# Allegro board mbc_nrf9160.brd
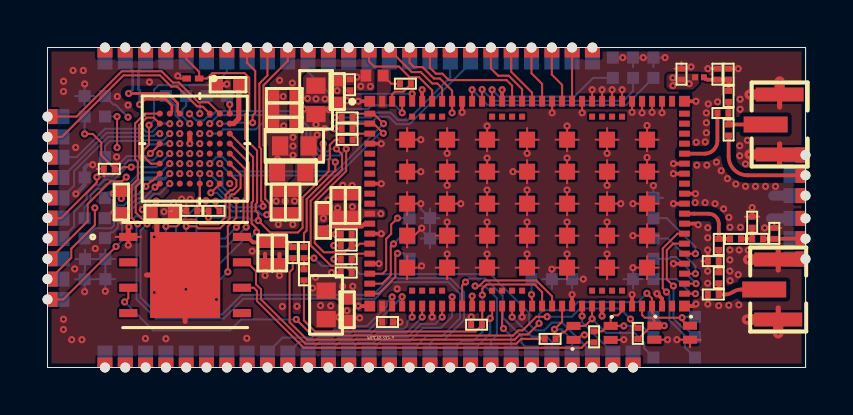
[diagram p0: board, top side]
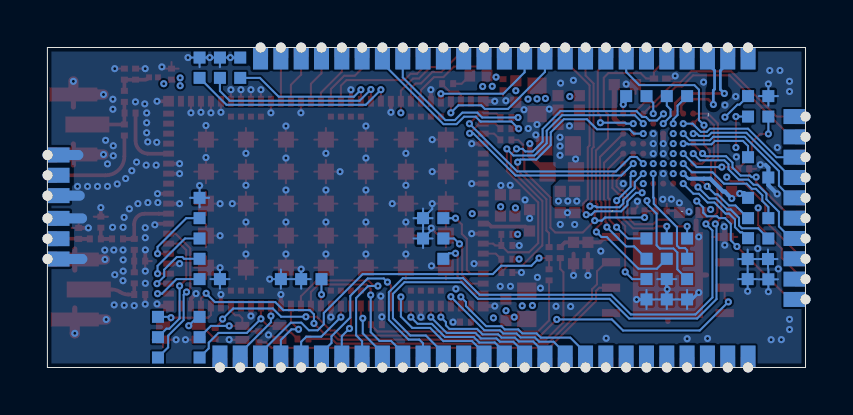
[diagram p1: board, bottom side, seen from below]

Outline 37.92 x 16 mm; copper layers: TOP, GND, POWER, BOTTOM. Coordinates in mm from the lower left corner of the outline.
Outline path: 0,16 0,0 37.92,0 37.92,16 0,16

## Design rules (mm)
constraint set DEFAULT: min track width 0.102
net group DIFFPAIR0: nets D+ D-

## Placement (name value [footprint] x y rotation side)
C1  39pF  [SMC0201]  33.51 14.94 270 top
C2  39pF  [SMC0201]  34.06 12.72 180 top
C3  15pF  [SMC0201]  15.13 13.86 90 top
C4  100nF  [SMC0402]  14.49 13.26 90 top
C5  47uF  [SMC0603]  13.43 12.67 90 top
C6  39pF  [SMC0201]  34.07 11.6 90 top
C7  100nF  [SMC0402]  14.54 8.64 270 top
C8  4.7uF  [SMC0402]  15.26 8.64 270 top
C9  4.7uF  [SMC0402]  13.8 7.89 270 top
C10  15pF  [SMC0201]  17.28 2.27 180 top
C11  100nF  [SMC0402]  14.99 3.42 270 top
C12  47uF  [SMC0603]  13.94 3.84 270 top
C13  100nF  [SMC0201]  21.19 2.14 0 top
C14  100nF  [SMC0201]  8.6 7.83 180 top
C15  100n  [SMC0402]  12.38 13.59 180 top
C16  100n  [SMC0402]  12.38 12.87 180 top
C17  100n  [SMC0402]  5.23 7.75 0 top
C18  100n  [SMC0402]  12.38 12.15 180 top
C19  10u  [SMC0603]  13.06 11.08 180 top
C20  100n  [SMC0402]  12.27 7.74 90 top
C21  1u  [SMC0402]  11.55 7.74 90 top
C22  100n  [SMC0402]  3.69 7.74 90 top
C23  4.7u  [SMC0402]  8.5 14.14 0 top
C24  100n  [SMC0402]  11.6 5.19 90 top
C25  1u  [SMC0402]  10.88 5.19 90 top
C65  TBD  [SMC0201]  35.25 6.43 0 top
C66  TBD  [SMC0201]  33.58 4.76 270 top
C67  680pF  [SMC0201]  31.71 14.94 270 top
C68  2.2nF  [SMC0201]  34.07 14.94 270 top
D1  PTVS5V5D1BLYL  [PESD5V0S1BL315]  26.31 1.73 90 top
D2  PTVS5V5D1BLYL  [PESD5V0S1BL315]  28.17 1.73 270 top
D3  PTVS5V5D1BLYL  [PESD5V0S1BL315]  30.36 1.74 270 top
D4  PTVS5V5D1BLYL  [PESD5V0S1BL315]  32.14 1.74 270 top
D5  ESDALC6V1-1U2  [DIODE_ESDALC6V1-1U2]  7.27 14.45 180 top
FL1  BLM15AX121SN1D  [BEADC1005X55N]  16.36 14.59 0 top
FL2  BLM02KX180SN1B  [BEADC0402X32N]  32.61 14.51 0 top
FL3  BLM18PG471SN1D  [SML0603]  11.48 9.78 0 top
J1  CON1  [MBC_PAD_CONN]  27.26 16 90 top
J2  CON1  [MBC_PAD_CONN]  26.24 16 90 top
J3  CON1  [MBC_PAD_CONN]  25.23 16 90 top
J4  CON1  [MBC_PAD_CONN]  24.21 16 90 top
J5  CON1  [MBC_PAD_CONN]  23.19 16 90 top
J6  CON1  [MBC_PAD_CONN]  22.18 16 90 top
J7  CON1  [MBC_PAD_CONN]  21.16 16 90 top
J8  CON1  [MBC_PAD_CONN]  20.15 16 90 top
J9  CON1  [MBC_PAD_CONN]  19.13 16 90 top
J10  CON1  [MBC_PAD_CONN]  18.11 16 90 top
J11  CON1  [MBC_PAD_CONN]  17.1 16 90 top
J12  CON1  [MBC_PAD_CONN]  16.08 16 90 top
J13  CON1  [MBC_PAD_CONN]  15.07 16 90 top
J14  CON1  [MBC_PAD_CONN]  14.05 16 90 top
J15  CON1  [MBC_PAD_CONN]  13.03 16 90 top
J16  CON1  [MBC_PAD_CONN]  12.02 16 90 top
J17  CON1  [MBC_PAD_CONN]  11 16 90 top
J18  CON1  [MBC_PAD_CONN]  9.99 16 90 top
J19  CON1  [MBC_PAD_CONN]  8.97 16 90 top
J20  CON1  [MBC_PAD_CONN]  7.95 16 90 top
J21  CON1  [MBC_PAD_CONN]  6.94 16 90 top
J22  CON1  [MBC_PAD_CONN]  5.92 16 90 top
J23  CON1  [MBC_PAD_CONN]  4.91 16 90 top
J24  CON1  [MBC_PAD_CONN]  3.89 16 90 top
J25  CON1  [MBC_PAD_CONN]  2.87 16 90 top
J26  CON1  [MBC_PAD_CONN]  0 12.55 180 top
J27  CON1  [MBC_PAD_CONN]  0 11.53 180 top
J28  CON1  [MBC_PAD_CONN]  0 10.52 180 top
J29  CON1  [MBC_PAD_CONN]  0 9.5 180 top
J30  CON1  [MBC_PAD_CONN]  0 8.48 180 top
J31  CON1  [MBC_PAD_CONN]  0 7.47 180 top
J32  CON1  [MBC_PAD_CONN]  0 6.45 180 top
J33  CON1  [MBC_PAD_CONN]  0 5.43 180 top
J34  CON1  [MBC_PAD_CONN]  0 4.42 180 top
J35  CON1  [MBC_PAD_CONN]  0 3.4 180 top
J36  CON1  [MBC_PAD_CONN]  2.88 0 270 top
J37  CON1  [MBC_PAD_CONN]  3.89 0 270 top
J38  CON1  [MBC_PAD_CONN]  4.91 0 270 top
J39  CON1  [MBC_PAD_CONN]  5.92 0 270 top
J40  CON1  [MBC_PAD_CONN]  6.94 0 270 top
J41  CON1  [MBC_PAD_CONN]  7.96 0 270 top
J42  CON1  [MBC_PAD_CONN]  8.97 0 270 top
J43  CON1  [MBC_PAD_CONN]  9.99 0 270 top
J44  CON1  [MBC_PAD_CONN]  11 0 270 top
J45  CON1  [MBC_PAD_CONN]  12.02 0 270 top
J46  CON1  [MBC_PAD_CONN]  13.04 0 270 top
J47  CON1  [MBC_PAD_CONN]  14.05 0 270 top
J48  CON1  [MBC_PAD_CONN]  15.07 0 270 top
J49  CON1  [MBC_PAD_CONN]  16.08 0 270 top
J50  CON1  [MBC_PAD_CONN]  17.1 0 270 top
J51  CON1  [MBC_PAD_CONN]  18.11 0 270 top
J52  CON1  [MBC_PAD_CONN]  19.13 0 270 top
J53  CON1  [MBC_PAD_CONN]  20.15 0 270 top
J54  CON1  [MBC_PAD_CONN]  21.16 0 270 top
J55  CON1  [MBC_PAD_CONN]  22.18 0 270 top
J56  CON1  [MBC_PAD_CONN]  23.2 0 270 top
J57  CON1  [MBC_PAD_CONN]  24.21 0 270 top
J58  CON1  [MBC_PAD_CONN]  25.23 0 270 top
J59  CON1  [MBC_PAD_CONN]  26.24 0 270 top
J60  CON1  [MBC_PAD_CONN]  27.26 0 270 top
J61  CON1  [MBC_PAD_CONN]  28.27 0 270 top
J62  CON1  [MBC_PAD_CONN]  29.29 0 270 top
J63  CON1  [MBC_PAD_CONN]  37.92 6.44 0 top
J64  CON1  [MBC_PAD_CONN]  37.91 9.61 0 top
J65  UFL  [U_FL-R-SMT-1]  36.55 3.9 180 top
J66  UFL  [U_FL-R-SMT-1]  36.62 12.15 180 top
J67  CON1  [MBC_PAD_CONN]  37.91 5.42 0 top
J68  CON1  [MBC_PAD_CONN]  37.91 7.46 0 top
J69  CON1  [MBC_PAD_CONN]  37.91 10.62 0 top
J70  CON1  [MBC_PAD_CONN]  37.91 8.59 0 top
J72  CON1  [MBC_LGA_SMALL_PAD]  7.95 13.57 180 bottom
J73  CON1  [MBC_LGA_SMALL_PAD]  2.87 12.55 180 bottom
J74  CON1  [MBC_LGA_SMALL_PAD]  2.87 7.47 180 bottom
J75  CON1  [MBC_LGA_SMALL_PAD]  5.92 4.42 180 bottom
J76  CON1  [MBC_LGA_SMALL_PAD]  5.92 5.43 180 bottom
J77  CON1  [MBC_LGA_SMALL_PAD]  7.95 5.43 180 bottom
J78  CON1  [MBC_LGA_SMALL_PAD]  6.94 5.43 180 bottom
J81  CON1  [MBC_LGA_SMALL_PAD]  1.86 9.5 180 bottom
J82  CON1  [MBC_LGA_SMALL_PAD]  7.95 3.4 180 bottom
J83  CON1  [MBC_LGA_SMALL_PAD]  2.87 10.52 180 bottom
J84  CON1  [MBC_LGA_SMALL_PAD]  2.87 8.48 180 bottom
J85  CON1  [MBC_LGA_SMALL_PAD]  6.94 13.57 180 bottom
J86  CON1  [MBC_LGA_SMALL_PAD]  7.95 4.42 180 bottom
J87  CON1  [MBC_LGA_SMALL_PAD]  5.92 13.57 180 bottom
J88  CON1  [MBC_LGA_SMALL_PAD]  5.92 6.45 90 bottom
J89  CON1  [MBC_LGA_SMALL_PAD]  2.87 13.57 180 bottom
J90  CON1  [MBC_LGA_SMALL_PAD]  6.94 6.45 90 bottom
J91  CON1  [MBC_LGA_SMALL_PAD]  1.86 7.47 180 bottom
J93  CON1  [MBC_LGA_SMALL_PAD]  8.97 13.57 180 bottom
J95  CON1  [MBC_LGA_SMALL_PAD]  1.86 12.55 180 bottom
J96  CON1  [MBC_LGA_SMALL_PAD]  7.95 6.45 90 bottom
J97  CON1  [MBC_LGA_SMALL_PAD]  1.86 6.45 180 bottom
J98  CON1  [MBC_LGA_SMALL_PAD]  2.89 5.42 180 bottom
J99  CON1  [MBC_LGA_SMALL_PAD]  2.87 6.47 180 bottom
J100  CON1  [MBC_LGA_SMALL_PAD]  1.88 5.42 180 bottom
J101  CON1  [MBC_LGA_SMALL_PAD]  1.86 13.57 180 bottom
J102  CON1  [MBC_LGA_SMALL_PAD]  1.86 4.41 180 bottom
J103  CON1  [MBC_LGA_SMALL_PAD]  18.11 7.47 180 bottom
J104  CON1  [MBC_LGA_SMALL_PAD]  5.92 3.4 180 bottom
J105  CON1  [MBC_LGA_SMALL_PAD]  18.11 6.45 180 bottom
J106  CON1  [MBC_LGA_SMALL_PAD]  2.89 4.42 180 bottom
J107  CON1  [MBC_LGA_SMALL_PAD]  18.11 5.43 180 bottom
J108  CON1  [MBC_LGA_SMALL_PAD]  6.94 4.42 180 bottom
J109  CON1  [MBC_LGA_SMALL_PAD]  29.29 4.42 180 bottom
J110  CON1  [MBC_LGA_SMALL_PAD]  6.94 3.4 180 bottom
J111  CON1  [MBC_LGA_SMALL_PAD]  26.24 4.42 180 bottom
J112  CON1  [MBC_LGA_SMALL_PAD]  32.39 1.52 180 bottom
J113  CON1  [MBC_LGA_SMALL_PAD]  25.23 4.42 180 bottom
J114  CON1  [MBC_LGA_SMALL_PAD]  32.39 0.5 180 bottom
J115  CON1  [MBC_LGA_SMALL_PAD]  19.13 7.47 180 bottom
J116  CON1  [MBC_LGA_SMALL_PAD]  30.31 7.47 180 bottom
J117  CON1  [MBC_LGA_SMALL_PAD]  19.13 6.45 180 bottom
J118  CON1  [MBC_LGA_SMALL_PAD]  30.31 6.45 180 bottom
J119  CON1  [MBC_LGA_SMALL_PAD]  30.31 14.48 180 bottom
J120  CON1  [MBC_LGA_SMALL_PAD]  30.31 5.43 180 bottom
J121  CON1  [MBC_LGA_SMALL_PAD]  29.29 14.48 180 bottom
J122  CON1  [MBC_LGA_SMALL_PAD]  30.31 4.42 180 bottom
J123  CON1  [MBC_LGA_SMALL_PAD]  28.27 14.48 180 bottom
J124  CON1  [MBC_LGA_SMALL_PAD]  24.21 4.42 180 bottom
J125  CON1  [MBC_LGA_SMALL_PAD]  30.31 15.5 180 bottom
J126  CON1  [MBC_LGA_SMALL_PAD]  30.31 0.5 180 bottom
J127  CON1  [MBC_LGA_SMALL_PAD]  29.29 15.5 180 bottom
J128  CON1  [MBC_LGA_SMALL_PAD]  30.31 1.52 180 bottom
J129  CON1  [MBC_LGA_SMALL_PAD]  28.27 15.5 180 bottom
J130  CON1  [MBC_LGA_SMALL_PAD]  30.31 2.53 180 bottom
J131  CON1  [MBC_LGA_SMALL_PAD]  32.39 2.53 180 bottom
J132  CON1  [MBC_LGA_SMALL_PAD]  30.31 8.48 180 bottom
L1  68nH  [SML0201]  34.07 13.28 90 top
L2  TBD  [SML0201]  35.25 6.99 90 top
L3  TBD  [SML0201]  36.36 6.43 90 top
L4  TBD  [SML0201]  33.58 5.32 180 top
L5  TBD  [SML0201]  33.58 3.65 180 top
R1  100  [SMR0201]  15.26 12.5 180 top
R2  100  [SMR0201]  15.26 11.94 180 top
R3  10k  [SMR0201]  17.63 14.19 0 top
R4  1k  [SMR0201]  14.71 11.38 0 top
R5  1k  [SMR0201]  12.83 4.36 90 top
R6  220  [SMR0201]  12.83 5.47 90 top
R7  10k  [SMR0201]  2.81 9.94 0 top
R8  100k  [SMR0201]  7.49 7.83 180 top
R9  0R  [SMR0201]  34.69 6.43 180 top
R10  0R  [SMR0201]  33.58 6.43 270 top
R21  100k  [SMR0201]  15.22 6.66 180 top
R22  100k  [SMR0201]  15.22 5.42 180 top
R23  NM  [SMR0201]  14.67 6.1 0 top
R24  NM  [SMR0201]  14.67 4.75 0 top
R25  0  [SMR0201]  25.41 1.43 180 top
R26  0  [SMR0201]  27.34 1.81 270 top
R27  0  [SMR0201]  29.53 1.43 90 top
R28  0  [SMR0201]  12.27 5.47 90 top
U1  NRF9160-SICA-R  [XCVR_NRF9160-SICA-R]  23.99 8.19 0 top
U3  ST4SIM-200M  [SON_IM-200M_STM]  6.89 4.62 0 top
U4  STM32U545REI6  [UFBGA64_5X5MM_STM]  7.37 10.94 90 top

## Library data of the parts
C1-C25 C67 C68 = C
C65 C66 = CAP NP_1
D1-D4 = PTVS5V5D1BLYL_0
D5 = ESDALC6V1-1U2
FL1 = BLM15AX121SN1D
FL2 = BLM02KX180SN1B
FL3 L2-L5 = INDUCTOR
J1-J64 J67-J70 J72-J78 J81-J91 J93 J95-J132 = CON1_2
J65 J66 = UFL
L1 = L
R1-R3 R5 R7-R10 R21-R28 = R
R4 R6 = R_0
U1 = myNRF9160-SICA-R_6
U3 = ST4SIM-200M_8: User Part Number: PN; Tolerance: TOL
U4 = STM32U545REI6_13: User Part Number: PN; Tolerance: TOL

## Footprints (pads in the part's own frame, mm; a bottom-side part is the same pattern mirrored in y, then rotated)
BEADC0402X32N
  rect 0.29x0.3 smd: 1(-0.222,0) 2(0.222,0)
BEADC1005X55N
  rect 0.54x0.6 smd: 1(-0.432,0) 2(0.432,0)
DIODE_ESDALC6V1-1U2
  rect 0.425x0.3 smd: 1(-0.312,0) 2(0.312,0)
MBC_LGA_SMALL_PAD
  rect 0.6x0.6 smd: 1(0,0)
MBC_PAD_CONN
  rect 0.5x0.75 hole 0.6: 1(0,0)
PESD5V0S1BL315
  rect 0.4x0.7 smd: 1(-0.35,0) 2(0.35,0)
SMC0201
  rect 0.3x0.35 smd: 1(0,0) 2(0.55,0)
SMC0402
  rect 0.559x0.559 smd: 1(0,0) 2(1.067,0)
SMC0603
  rect 0.813x0.965 smd: 1(0,0) 2(1.422,0)
SML0201
  rect 0.3x0.35 smd: 1(0,0) 2(0.55,0)
SML0603
  rect 0.813x0.965 smd: 1(0,0) 2(1.422,0)
SMR0201
  rect 0.3x0.35 smd: 1(0,0) 2(0.55,0)
SON_IM-200M_STM
  rect 0.91x0.407 smd: 1(-2.842,1.905) 2(-2.842,0.635) 3(-2.842,-0.635) 4(-2.842,-1.905) 5(2.842,-1.905) 6(2.842,-0.635) 7(2.842,0.635) 8(2.842,1.905)
  rect 3.505x4.293 smd: 9(0,0)
U_FL-R-SMT-1
  rect 2.4x0.7 smd: 1(0,1.5) 3(0,-1.5)
  rect 2.2x0.8 smd: 2(0.7,0)
UFBGA64_5X5MM_STM
  round 0.305 smd: A1(-1.75,1.75) A2(-1.25,1.75) A3(-0.75,1.75) A4(-0.25,1.75) A5(0.25,1.75) A6(0.75,1.75) A7(1.25,1.75) A8(1.75,1.75) B1(-1.75,1.25) B2(-1.25,1.25) B3(-0.75,1.25) B4(-0.25,1.25) B5(0.25,1.25) B6(0.75,1.25) B7(1.25,1.25) B8(1.75,1.25) C1(-1.75,0.75) C2(-1.25,0.75) C3(-0.75,0.75) C4(-0.25,0.75) C5(0.25,0.75) C6(0.75,0.75) C7(1.25,0.75) C8(1.75,0.75) D1(-1.75,0.25) D2(-1.25,0.25) D3(-0.75,0.25) D4(-0.25,0.25) D5(0.25,0.25) D6(0.75,0.25) D7(1.25,0.25) D8(1.75,0.25) E1(-1.75,-0.25) E2(-1.25,-0.25) E3(-0.75,-0.25) E4(-0.25,-0.25) E5(0.25,-0.25) E6(0.75,-0.25) E7(1.25,-0.25) E8(1.75,-0.25) F1(-1.75,-0.75) F2(-1.25,-0.75) F3(-0.75,-0.75) F4(-0.25,-0.75) F5(0.25,-0.75) F6(0.75,-0.75) F7(1.25,-0.75) F8(1.75,-0.75) G1(-1.75,-1.25) G2(-1.25,-1.25) G3(-0.75,-1.25) G4(-0.25,-1.25) G5(0.25,-1.25) G6(0.75,-1.25) G7(1.25,-1.25) G8(1.75,-1.25) H1(-1.75,-1.75) H2(-1.25,-1.75) H3(-0.75,-1.75) H4(-0.25,-1.75) H5(0.25,-1.75) H6(0.75,-1.75) H7(1.25,-1.75) H8(1.75,-1.75)
XCVR_NRF9160-SICA-R
  rect 0.54x0.54 smd: 1(-7.87,5.12) 21(-7.87,-5.12) 52(7.87,-5.12) 72(7.87,5.12)
  rect 0.54x0.3 smd: 2(-7.87,4.5) 3(-7.87,4) 4(-7.87,3.5) 5(-7.87,3) 6(-7.87,2.5) 7(-7.87,2) 8(-7.87,1.5) 9(-7.87,1) 10(-7.87,0.5) 11(-7.87,0) 12(-7.87,-0.5) 13(-7.87,-1) 14(-7.87,-1.5) 15(-7.87,-2) 16(-7.87,-2.5) 17(-7.87,-3) 18(-7.87,-3.5) 19(-7.87,-4) 20(-7.87,-4.5) 53(7.87,-4.5) 54(7.87,-4) 55(7.87,-3.5) 56(7.87,-3) 57(7.87,-2.5) 58(7.87,-2) 59(7.87,-1.5) 60(7.87,-1) 61(7.87,-0.5) 62(7.87,0) 63(7.87,0.5) 64(7.87,1) 65(7.87,1.5) 66(7.87,2) 67(7.87,2.5) 68(7.87,3) 69(7.87,3.5) 70(7.87,4) 71(7.87,4.5)
  rect 0.3x0.54 smd: 22(-7.25,-5.12) 23(-6.75,-5.12) 24(-6.25,-5.12) 25(-5.75,-5.12) 26(-5.25,-5.12) 27(-4.75,-5.12) 28(-4.25,-5.12) 29(-3.75,-5.12) 30(-3.25,-5.12) 31(-2.75,-5.12) 32(-2.25,-5.12) 33(-1.75,-5.12) 34(-1.25,-5.12) 35(-0.75,-5.12) 36(-0.25,-5.12) 37(0.25,-5.12) 38(0.75,-5.12) 39(1.25,-5.12) 40(1.75,-5.12) 41(2.25,-5.12) 42(2.75,-5.12) 43(3.25,-5.12) 44(3.75,-5.12) 45(4.25,-5.12) 46(4.75,-5.12) 47(5.25,-5.12) 48(5.75,-5.12) 49(6.25,-5.12) 50(6.75,-5.12) 51(7.25,-5.12) 73(7.25,5.12) 74(6.75,5.12) 75(6.25,5.12) 76(5.75,5.12) 77(5.25,5.12) 78(4.75,5.12) 79(4.25,5.12) 80(3.75,5.12) 81(3.25,5.12) 82(2.75,5.12) 83(2.25,5.12) 84(1.75,5.12) 85(1.25,5.12) 86(0.75,5.12) 87(0.25,5.12) 88(-0.25,5.12) 89(-0.75,5.12) 90(-1.25,5.12) 91(-1.75,5.12) 92(-2.25,5.12) 93(-2.75,5.12) 94(-3.25,5.12) 95(-3.75,5.12) 96(-4.25,5.12) 97(-4.75,5.12) 98(-5.25,5.12) 99(-5.75,5.12) 100(-6.25,5.12) 101(-6.75,5.12) 102(-7.25,5.12)
  rect 0.8x0.8 smd: 103_1(-6,3.2) 103_2(-4,3.2) 103_3(-2,3.2) 103_4(0,3.2) 103_5(2,3.2) 103_6(4,3.2) 103_7(6,3.2) 103_8(-6,1.6) 103_9(-4,1.6) 103_10(-2,1.6) 103_11(0,1.6) 103_12(2,1.6) 103_13(4,1.6) 103_14(6,1.6) 103_15(-6,0) 103_16(-4,0) 103_17(-2,0) 103_18(0,0) 103_19(2,0) 103_20(4,0) 103_21(6,0) 103_22(-6,-1.6) 103_23(-4,-1.6) 103_24(-2,-1.6) 103_25(0,-1.6) 103_26(2,-1.6) 103_27(4,-1.6) 103_28(6,-1.6) 103_29(-6,-3.2) 103_30(-4,-3.2) 103_31(-2,-3.2) 103_32(0,-3.2) 103_33(2,-3.2) 103_34(4,-3.2) 103_35(6,-3.2)
  rect 0.3x0.3 smd: 104(-5.75,-4.35) 105(-5.25,-4.35) 106(-4.75,-4.35) 107(-4.25,-4.35) 108(-1.75,-4.35) 109(-1.25,-4.35) 110(-0.75,-4.35) 111(-0.25,-4.35) 112(3.25,-4.35) 113(3.75,-4.35) 114(4.25,-4.35) 115(4.75,-4.35) 116(4.75,4.35) 117(4.25,4.35) 118(3.75,4.35) 119(3.25,4.35) 120(-0.25,4.35) 121(-0.75,4.35) 122(-1.25,4.35) 123(-1.75,4.35) 124(-4.25,4.35) 125(-4.75,4.35) 126(-5.25,4.35) 127(-5.75,4.35)

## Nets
GND: C1.1 C3.1 C4.1 C5.1 C7.1 C8.1 C9.1 C10.1 C11.1 C12.1 C13.1 C14.1 C15.1 C16.1 C17.1 C18.1 C19.1 C20.1 C21.1 C22.1 C23.1 C24.1 C25.1 C67.1 C68.1 D1.1 D2.2(K2) D3.2(K2) D4.2(K2) D5.2 J1.1 J13.1 J22.1 J25.1 J38.1 J39.1 J43.1 J50.1 J62.1 J65.1 J65.3 J66.1 J66.3 J67.1 J68.1 J69.1 J70.1 J81.1 J82.1 J98.1 J100.1 J101.1 J102.1 J104.1 J106.1 J108.1 J109.1 J110.1 J111.1 J113.1 J115.1 J117.1 J125.1 J127.1 J129.1 J132.1 L2.2 L3.2 L4.2 L5.2 R7.1 R23.1 R24.1 U1.1 U1.5 U1.9 U1.14 U1.17 U1.21 U1.27 U1.31 U1.36 U1.41 U1.44 U1.47 U1.50 U1.52 U1.56 U1.60 U1.62 U1.63 U1.65 U1.66 U1.72 U1.74 U1.75 U1.76 U1.77 U1.78 U1.79 U1.80 U1.81 U1.82 U1.85 U1.90 U1.94 U1.98 U1.103_1(VSS#103_1) U1.103_2 U1.103_3 U1.103_4 U1.103_5 U1.103_6 U1.103_7 U1.103_8 U1.103_9 U1.103_10 U1.103_11 U1.103_12 U1.103_13 U1.103_14 U1.103_15 U1.103_16 U1.103_17 U1.103_18 U1.103_19 U1.103_20 U1.103_21 U1.103_22 U1.103_23 U1.103_24 U1.103_25 U1.103_26 U1.103_27 U1.103_28 U1.103_29 U1.103_30 U1.103_31 U1.103_32 U1.103_33 U1.103_34 U1.103_35 U3.1 U3.9 U4.C2 U4.D4 U4.D5 U4.D6(VSS_4) U4.F1
VBAT: C22.2 J84.1 U4.B2
VDD: FL1.2 R3.1 U1.102
VDD NRF91: C3.2 C4.2 C5.2 C7.2 C8.2 C10.2 C11.2 C12.2 C67.2 FL1.1 FL2.1 J40.1 J41.1 J42.1 R21.2 R22.2 U1.12 U1.22
VDD_RF: C1.2 C68.2 FL2.2 L1.2
VDD_ST: C15.2 C16.2 C17.2 C18.2 C19.2 FL3.1 J36.1 J37.1 R8.2 U4.D2 U4.E4 U4.E5 U4.E6
VDDA_ST: C20.2 C21.2 FL3.2 J20.1 U4.H1
A0_N: J44.1 U1.23
A1_N: J45.1 U1.24
A2_N: J46.1 U1.25
A3_N: J47.1 U1.26
A4_N: J48.1 U1.28
A5_N: J49.1 U1.29
A6_N: J57.1 U1.30
A7_N: J58.1 U1.35
COEX0: J119.1 U1.93
COEX1: J121.1 U1.92
COEX2: J123.1 U1.91
D+: J23.1 U4.B8
D-: J24.1 U4.C8
ENABLE: R3.2 U1.101
ESIM_1V8: C24.2 C25.2 R28.2 U3.8(VCC)
ESIM_CLK: R26.2 U3.6
ESIM_IO: R27.2 U3.3
ESIM_RST: R25.2 U3.7
IO_SUPPLY_RSV: C9.2 U1.13
MAGPIO0: J118.1 U1.55
MAGPIO1: J120.1 U1.54
MAGPIO2: J122.1 U1.53
N_U545_NRST: R4.2 U1.4
NORDICRST: C13.2 R5.1 U1.32
NRF91_INT: R21.1 R23.2 U1.15 U4.F7
NRF91_RSTN: J60.1 R5.2 R6.1
NRF91_SWDCLK: J54.1 U1.33
NRF91_SWDIO: J56.1 U1.34
NRF91RST: R6.2 U4.F6
NRX: J8.1 R1.2
NTX: J7.1 R2.2
NTX_SRX: R2.1 U1.3 U4.G3
OSC32_IN: J97.1 U4.A1
OSC32_OUT: J99.1 U4.B1
OSC_IN: U4.C1
OSC_OUT: U4.D1
P0.00: J10.1 U1.95
P0.01: J11.1 U1.96
P0.02: J12.1 U1.97
P0.03: J14.1 U1.99
P0.04: J15.1 U1.100
P0.10: J103.1 U1.18
P0.11: J105.1 U1.19
P0.12: J107.1 U1.20
P0.21: J124.1 U1.37
P0.22: J53.1 U1.38
P0.23: J55.1 U1.39
P0.24: J59.1 U1.40
P0.25: J61.1 U1.42
P0.26: J2.1 U1.83
P0.27: J3.1 U1.84
P0.28: J4.1 U1.86
P0.29: J5.1 U1.87
P0.30: J6.1 U1.88
P0.31: J9.1 U1.89
PA0: J86.1 U4.G2
PA1: J88.1 U4.H2
PA4: J90.1 U4.H3
PA5: U4.F4
PA6: U4.G4
PA7: J96.1 U4.H4
PA8: J85.1 U4.D7
PA9: J87.1 U4.C7
PA10: J89.1 U4.C6
PA15: J29.1 U4.A6
PB0: U4.F5
PB1: U4.G5
PB2: U4.G6
PB3: J31.1 U4.A5
PB4: J32.1 U4.A4
PB5: J33.1 U4.C4
PB6: J35.1 U4.D3
PB7: J34.1 U4.C3
PB8: J91.1 U4.B3
PB9: J19.1 U4.A3
PB10: J18.1 U4.G7
PB12: J93.1 U4.H8
PB13: J26.1 U4.G8
PB14: J27.1 U4.F8
PC0: J75.1 U4.E3
PC1: J76.1 U4.E2
PC2: J17.1 U4.F2
PC3: J16.1 U4.G1
PC4: J77.1 U4.H5
PC5: J78.1 U4.H6
PC7: U4.E7
PC8: J72.1 U4.E8
PC10: J28.1 U4.B7
PC11: J30.1 U4.B6
PC12: J73.1 U4.C5
PC13: J74.1 U4.A2
PD2: J83.1 U4.B5
PH3: J95.1 R7.2 U4.B4
SCLK: J112.1 U1.58
SDATA: J114.1 U1.59
SIM_1V8: D4.1 J131.1 R28.1 U1.49
SIM_CLK: D2.1 J128.1 R26.1 U1.46
SIM_IO: D3.1 J130.1 R27.1 U1.48
SIM_RST: D1.2(K2) J126.1 R25.1 U1.43
STX_NRX: R1.1 U1.2 U4.F3
U545_INT: R22.1 R24.2 U1.16 U4.D8
U545_NRST: C14.2 D5.1(K) J21.1 R4.1 R8.1 U4.E1
U545_SWDCLK: J52.1 U4.A7
U545_SWDIO: J51.1 U4.A8
VCAP: C23.2 U4.H7
VIO: J116.1 U1.57
N13496579: C2.2 U1.67
N13625908: C66.2 J65.2(RF) L5.1
N13629219: C65.2 J63.1 L3.1
N13629615: C2.1 C6.2 J66.2(RF) L1.1
N13629622: C6.1 J64.1
N13657158: R9.2 R10.1 U1.61
N13657162: C65.1 L2.1 R9.1
N13659178: C66.1 L4.1 R10.2

Pads without a net: U1 6 7 8 10 11 45 51 64 68 69 70 71 73 104 105 106 107 108 109 110 111 112 113 114 115 116 117 118 119 120 121 122 123 124 125 126 127; U3 2 4 5

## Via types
v1: diameter 0.36, hole 0.15, TOP to BOTTOM, 351 vias

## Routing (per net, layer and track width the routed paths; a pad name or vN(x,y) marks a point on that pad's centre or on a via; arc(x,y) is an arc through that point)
GND: length 218.8
  TOP w0.102: 25.41,4.99 U1.103_33 ; U1.103_33 26.57,4.99 ; U1.103_33 25.99,4.41 ; U1.103_33 v1(25.99,5.67) ; 21.99,6.01 U1.103_24 ; U1.103_24 21.41,6.59 ; U1.103_24 v1(21.99,7.27) ; U1.103_24 22.57,6.59 ; U1.103_31 22.57,4.99 ; U1.103_31 21.41,4.99 ; U1.103_31 v1(21.99,5.67) ; 33.03,4.97 L4.2 32.7,5.32 ; v1(8.41,8.31) 8.41,8.02 C14.1 ; 19.99,7.61 U1.103_16 ; U1.103_16 19.99,8.77 ; U1.103_16 v1(20.67,8.19) ; U1.103_16 19.41,8.19 ; C67.1 32.1,14.94 32.19,15.03 v1(32.19,15.03) ; C67.1 31.36,14.94 ; C67.1 31.71,15.27 ; U1.103_4 v1(23.99,10.71) ; U1.103_4 23.41,11.39 ; U1.103_4 24.57,11.39 ; U1.103_4 23.99,11.97 ; U1.103_9 v1(19.99,9.11) ; U1.103_9 20.57,9.79 ; U1.103_9 19.41,9.79 ; U1.103_9 19.99,10.37 ; 19.99,6.01 U1.103_23 ; U1.103_23 19.41,6.59 ; U1.103_23 20.57,6.59 ; U1.103_23 v1(19.99,7.27) ; U1.103_17 22.57,8.19 ; U1.103_17 21.41,8.19 ; U1.103_17 v1(21.99,8.87) ; U1.103_17 21.99,7.61 ; D3.2 v1(31.01,1.39) ; U1.103_19 26.57,8.19 ; U1.103_19 v1(25.99,8.87) ; U1.103_19 25.41,8.19 ; U1.103_19 25.99,7.61 ; 32.14,1.01 D4.2 ; D4.2 v1(31.48,1.39) ; D4.2 32.67,1.39 ; 19.99,4.41 U1.103_30 ; U1.103_30 19.41,4.99 ; U1.103_30 v1(19.99,5.67) ; U1.103_30 20.57,4.99 ; 34.89,7.54 L2.2 35.6,7.54 ; U1.103_21 30.57,8.19 ; U1.103_21 29.99,8.77 ; U1.103_21 v1(29.28,8.19) ; U1.103_21 29.99,7.61 ; 2.46,9.94 R7.1 2.81,9.57 2.85,9.54 ; 27.41,6.59 U1.103_27 ; U1.103_27 28.57,6.59 ; U1.103_27 27.99,6.01 ; U1.103_27 v1(27.99,7.27) ; 17.99,7.61 U1.103_15 ; U1.103_15 17.99,8.77 ; U1.103_15 17.41,8.19 ; U1.103_15 v1(18.67,8.19) ; 25.99,9.21 U1.103_12 ; U1.103_12 26.57,9.79 ; U1.103_12 v1(25.99,10.47) ; U1.103_12 25.41,9.79 ; U1.103_6 28.57,11.39 ; U1.103_6 27.99,11.97 ; U1.103_6 v1(27.99,10.71) ; U1.103_6 27.41,11.39 ; U1.103_10 22.57,9.79 ; U1.103_10 21.41,9.79 ; U1.103_10 21.99,9.21 ; U1.103_10 v1(21.99,10.47) ; U1.103_25 24.57,6.59 ; U1.103_25 23.99,6.01 ; U1.103_25 23.41,6.59 ; U1.103_25 v1(23.99,7.27) ; U1.103_3 v1(21.99,12.07) ; U1.103_3 22.57,11.39 ; U1.103_3 21.99,10.81 ; U1.103_3 21.41,11.39 ; U1.103_11 23.99,10.37 ; U1.103_11 24.57,9.79 ; U1.103_11 v1(23.28,9.79) ; U1.103_11 23.99,9.21 ; U1.103_2 19.99,11.97 ; U1.103_2 20.57,11.39 ; U1.103_2 v1(19.99,10.71) ; U1.103_2 19.41,11.39 ; U1.103_14 v1(29.99,10.5) ; U1.103_14 29.99,9.21 ; U1.103_14 30.57,9.79 ; U1.103_14 29.41,9.79 ; U1.103_13 27.99,10.37 ; U1.103_13 27.41,9.79 ; U1.103_13 v1(27.99,9.11) ; U1.103_13 28.57,9.79 ; U1.103_29 17.99,5.57 ; U1.103_29 17.99,4.41 ; U1.103_29 18.62,4.99 v1(18.71,5.08) ; 27.41,4.99 U1.103_34 ; U1.103_34 28.57,4.99 ; U1.103_34 v1(27.99,5.67) ; U1.103_34 27.99,4.41 ; 23.99,7.61 U1.103_18 ; U1.103_18 24.57,8.19 ; U1.103_18 23.41,8.19 ; U1.103_18 v1(23.99,8.87) ; v1(28.83,1.39) 28.81,1.38 D2.2 ; 29.99,10.81 U1.103_7 ; U1.103_7 29.41,11.39 ; U1.103_7 30.57,11.39 ; U1.103_7 v1(29.99,12.1) ; 25.41,11.39 U1.103_5 ; U1.103_5 26.57,11.39 ; U1.103_5 25.99,10.81 ; U1.103_5 v1(25.99,12.07) ; U1.103_8 17.99,10.37 ; U1.103_8 17.99,9.21 ; U1.103_8 v1(18.67,9.79) ; U1.103_8 17.41,9.79 ; 29.99,6.01 U1.103_28 ; U1.103_28 v1(29.28,6.59) ; U1.103_28 30.57,6.59 ; U1.103_28 29.99,7.17 ; U1.103_26 26.57,6.59 ; U1.103_26 v1(25.99,7.27) ; U1.103_26 25.99,6.01 ; U1.103_26 25.41,6.59 ; U1.103_20 27.99,8.77 ; U1.103_20 27.99,7.61 ; U1.103_20 27.41,8.19 ; U1.103_20 v1(28.67,8.19) ; U1.17 16.13,5.19 ; U1.79 v1(28.24,13.89) ; 36.71,6.98 L3.2 36.36,7.31 ; v1(21.19,2.53) 21.19,2.53 C13.1 ; C68.1 v1(34.55,14.94) ; 8.04,14.14 C23.1 8.5,13.68 ; U1.103_35 29.99,5.57 ; U1.103_35 v1(29.28,4.99) ; U1.103_35 30.57,4.99 ; U1.103_35 29.99,4.41 ; 3.41,6.53 U3.1 4.68,6.53 ; C3.1 15.13,13.59 ; 17.99,10.81 U1.103_1 ; U1.103_1 17.99,11.97 ; U1.103_1 v1(18.67,11.39) ; U1.103_1 17.41,11.39 ; U1.76 v1(29.74,12.73) ; U1.81 v1(27.24,13.89) ; U1.75 v1(30.24,12.76) ; U1.85 v1(25.24,12.73) ; D5.2 6.65,14.45 v1(6.52,14.58) ; U1.82 v1(26.74,12.73) ; U1.103_32 v1(23.99,5.67) ; U1.103_32 23.41,4.99 ; U1.103_32 24.57,4.99 ; U1.103_22 18.34,6.59 v1(18.72,6.97) ; U1.103_22 17.99,6.01 ; U1.103_22 17.99,7.17 ; U1.80 v1(27.74,13.89) ; U1.74 v1(30.74,12.73) ; R24.1 v1(14.21,4.75) ; C1.1 v1(33.03,14.94) ; U1.77 v1(29.24,12.76) ; v1(14.32,6.1) R23.1 ; v1(26.86,1.63) 26.73,1.63 26.48,1.38 D1.1 ; U1.78 v1(28.74,13.89)
  TOP w0.188: L4.2 33.03,5.8 ; U1.14 v1(16.7,6.69) ; U1.66 v1(31.31,10.19) ; U1.41 v1(26.24,3.65) ; U1.56 v1(31.31,5.19) ; L3.2 v1(35.87,6.98) ; U1.5 v1(16.7,11.19) ; U1.50 30.74,3.44 v1(30.48,3.69) ; L5.2 v1(33.03,3.17) ; v1(18.74,13.89) U1.98 ; U1.65 v1(31.31,9.69) ; U1.31 21.24,3.57 v1(21.24,3.57) ; U1.94 v1(20.74,12.76) ; U1.9 v1(16.7,9.19) ; 16.13,5.19 v1(16.58,5.19) ; v1(15.54,13.31) U1.1 ; v1(22.74,13.89) U1.90 ; U1.72 v1(32.44,13.31) ; U1.62 v1(31.31,8.19) ; L2.2 v1(35.25,8) ; U1.63 v1(32.41,8.69) ; U1.27 v1(19.24,2.52) ; U1.52 32.32,3.07 32.43,3.18 v1(32.44,3.18) ; U1.36 v1(23.74,2.52) ; U1.44 v1(27.74,2.57) ; v1(29.24,3.65) U1.47 ; U1.60 32.41,7.19 ; v1(15.54,3.07) U1.21
  TOP w0.203: v1(10.88,4.6) C25.1 10.88,5.69 ; v1(11.6,4.6) C24.1 11.6,5.69 ; 3.69,7.25 C22.1 3.24,7.74 ; v1(4.04,6.12) 4.04,6.12 U3.1
  TOP w0.254: 36.55,4.87 J65.3 36.55,5.93 ; U3.9 4.95,4.62 ; U3.9 5.47,6.04 5.47,7.33 ; U3.9 6.89,2.3 ; J65.1 36.55,2.98 ; C23.1 8.94,14.14 v1(8.97,14.17) ; 36.62,11.18 J66.1 36.62,10.12 ; U3.1 4.04,7.02 v1(4.07,7.04) ; U4.D6 v1(7.12,11.19) ; J66.3 36.62,13.02
  TOP w0.508: v1(36.55,1.71) J65.1 v1(34.98,2.4) ; J66.1 v1(35.11,10.65) ; J65.3 v1(35.04,5.4) ; v1(35.11,13.65) J66.3 v1(36.62,14.31)
  GND w0.508: 5.92,14.16 J22.1 ; J62.1 29.29,1.21 ; 36.2,7.46 J68.1 ; 36.74,5.42 J67.1 ; 36.38,8.59 J70.1 ; 5.92,1.83 J39.1 ; 9.99,1.89 J43.1 ; 17.1,1.46 J50.1 ; 27.26,14.71 J1.1 ; J38.1 4.91,1.67 ; 2.87,14.19 J25.1 ; 36.58,10.62 J69.1 ; J13.1 15.07,15.25
  POWER w0.254: 29.29,0.85 J62.1 ; 10.75,1.01 9.99,0.25 J43.1 ; 17.1,0.94 J50.1 ; 5.92,15.1 J22.1 ; 5.61,0.96 4.91,0.26 J38.1 ; 2.87,15.14 J25.1 ; 27.26,15.28 J1.1 ; 15.07,15.27 J13.1 ; v1(5.92,1.44) 5.92,1.44 J39.1
  POWER w0.508: 36.31,5.42 J67.1 ; 36.29,8.59 J70.1 ; 36.83,10.62 J69.1 ; 36.15,7.46 J68.1
  BOTTOM w0.102: 19.13,6.99 J115.1 ; J115.1 18.67,7.93 v1(18.67,8.19) ; J115.1 18.65,7.47 ; J115.1 19.13,7.95 ; J115.1 19.61,7.47 ; 29.29,3.94 J109.1 ; J109.1 29.77,4.42 ; J109.1 28.81,4.42 ; J109.1 29.29,4.9 ; 28.81,15.5 J127.1 ; J127.1 v1(29.8,15.5) ; J127.1 29.29,15.02 ; J82.1 8.43,3.4 ; J82.1 7.48,3.4 ; J82.1 7.95,3.88 ; J82.1 7.95,2.92 ; J125.1 v1(30.89,15.5) ; J125.1 30.31,15.02 ; J125.1 29.83,15.5 ; J13.1 15.07,15.25 ; J113.1 v1(25.23,4.92) ; J113.1 25.7,4.42 ; J113.1 25.23,3.94 ; J113.1 24.75,4.42 ; J101.1 v1(1.86,14.18) ; J101.1 2.34,13.57 ; J101.1 1.38,13.57 ; J101.1 1.86,13.09 ; 6.46,4.42 J108.1 7.42,4.42 ; J106.1 2.89,4.9 ; J106.1 2.42,4.42 ; J106.1 3.37,4.42 ; J106.1 v1(2.89,3.81) ; J132.1 v1(30.31,9.1) ; J132.1 30.31,8.01 ; J132.1 29.83,8.48 ; J132.1 30.79,8.48 ; 19.13,5.97 J117.1 ; J117.1 18.65,6.45 ; J117.1 19.61,6.45 ; J117.1 18.72,6.86 v1(18.72,6.97) ; J117.1 19.13,6.93 ; J110.1 7.42,3.4 ; J110.1 6.46,3.4 ; J110.1 6.94,2.92 ; 5.92,2.92 J104.1 ; J104.1 5.92,3.88 ; J104.1 6.4,3.4 ; J102.1 v1(1.86,3.79) ; J102.1 2.34,4.41 ; J102.1 1.86,4.89 ; J102.1 1.38,4.41 ; J129.1 v1(28.77,15.5) ; J111.1 v1(26.8,4.42) ; J111.1 26.24,3.94 ; J111.1 26.24,4.9 ; J111.1 25.76,4.42 ; J98.1 3.37,5.42 ; J98.1 2.89,5.9 ; J98.1 2.42,5.42 ; J98.1 2.89,4.94 ; 1.4,5.42 J100.1 ; J100.1 1.88,4.94 ; J100.1 2.36,5.42 ; J100.1 1.88,5.9
  BOTTOM w0.152: J110.1 6.94,3.89 v1(6.92,3.91) 6.94,3.93 J108.1 ; v1(8.45,3.4) 8.44,3.39 7.96,3.39 J82.1 ; v1(5.34,3.75) 5.69,3.4 J104.1
  BOTTOM w0.203: 2,10.13 1.86,9.99 J81.1 1.86,9.12 v1(1.42,8.68)
  BOTTOM w0.508: J67.1 36.17,5.42 ; J69.1 36.38,10.62 ; J68.1 36.19,7.46 ; J70.1 36.3,8.59
  vias: v1(0.8,14.31) v1(0.8,13.8) v1(0.8,2.41) v1(0.8,1.9) v1(1.21,1.39) v1(1.28,14.85) v1(1.41,11) v1(1.36,4.93) v1(1.72,1.39) v1(1.79,14.85) v1(2.26,10.14) v1(2.39,5.95) v1(3.49,13.55) v1(3.46,10.53) v1(4.03,13.12) v1(4.75,7.9) v1(4.9,1.45) v1(5.1,14.27) v1(5.34,6.53) v1(6.62,9.69) v1(7.12,10.69) v1(8.12,9.19) v1(9.97,1.46) v1(10.24,5.82) v1(11.55,7.15) v1(11.61,14.36) v1(11.75,3.05) v1(11.91,7.74) v1(12.25,14.22) v1(12.27,7.15) v1(12.48,3.06) v1(12.82,12.92) v1(13.26,3.97) v1(13.43,12.15) v1(13.41,4.51) v1(13.49,11.63) v1(13.8,7.46) v1(13.87,11.95) v1(14.03,8.38) v1(14.08,12.89) v1(14.77,9.11) v1(14.76,4.06) v1(14.99,13.34) v1(15.24,9.1) v1(15.27,4.06) v1(17.49,3.93) v1(17.63,2.27) v1(32.4,8.25) v1(32.45,11.26) v1(32.48,10.12) v1(32.55,7.13) v1(32.9,11.28) v1(32.9,8.24) v1(33.05,13.18) v1(32.95,12.73) v1(32.95,12.24) v1(32.95,11.74) v1(32.98,10.12) v1(33.02,6.99) v1(33.02,6.49) v1(33.02,5.88) v1(33.02,4.82) v1(33.02,4.21) v1(33.39,8.19) v1(33.52,13.28) v1(33.46,10.27) v1(33.58,3.1) v1(33.7,9.84) v1(33.82,7.93) v1(34.01,9.45) v1(34.08,7.51) v1(34.13,7.01) v1(34.14,5.88) v1(34.13,5.38) v1(34.13,4.82) v1(34.14,4.34) v1(34.08,3.11) v1(34.43,9.18) v1(34.55,4.64) v1(34.65,13.41) v1(34.65,12.91) v1(34.62,11.09) v1(34.62,10.59) v1(34.6,5.88) v1(34.58,3.13) v1(34.66,7.01) v1(34.91,10.18) v1(34.91,9.06) v1(35.01,11.36) v1(35.05,5.87) v1(35.41,9.05) v1(35.91,9.05) v1(36.41,9.05)
VBAT: length 4.3
  TOP w0.203: C22.2 3.69,8.45 v1(3.69,8.45)
  TOP w0.254: v1(3.29,8.7) 3.59,8.7 C22.2
  BOTTOM w0.15: v1(6.12,9.69) 6.11,9.69 5.86,9.44
  BOTTOM w0.152: 5.73,9.44 5.86,9.44
  BOTTOM w0.203: 5.73,9.44 5.08,9.44 4.76,9.44 4.12,8.8 4.04,8.8 v1(3.69,8.45)
  BOTTOM w0.254: v1(3.29,8.7) 3.09,8.7 J84.1
VDD: length 1
  TOP w0.102: FL1.2 17.2,14.19 R3.1
VDD NRF91: length 0.6
  TOP w0.102: v1(14.4,6.66) R21.2 ; R22.2 14.66,5.42 v1(14.33,5.42)
  vias: v1(13.01,13.45) v1(13.43,13.43) v1(13.66,3.1) v1(13.88,13.42) v1(14.17,3.09) v1(14.49,13.84) v1(14.51,7.98) v1(14.57,2.52) v1(14.98,2.84) v1(15.25,8.04) v1(15.48,14.52) v1(15.61,2.48) v1(15.67,14.06) v1(16.15,14.05) v1(16.67,7.69) v1(31.28,14.48) v1(31.28,14.09) v1(32.1,14.19)
VDD_RF: length 1.8
  TOP w0.188: L1.2 C68.2 C1.2 33.03,14.39 arc(32.96,14.41) 32.9,14.45 FL2.2
VDD_ST: length 0.7
  TOP w0.102: 6.94,8.18 R8.2 6.62,7.83
  vias: v1(5.83,7.79) v1(6.31,8.23) v1(6.71,8.42) v1(7.12,9.69) v1(7.14,8.41) v1(7.62,11.69) v1(7.62,11.19) v1(7.62,10.69) v1(11.5,10.42) v1(11.79,13.55) v1(11.81,12.08) v1(12.28,11.51) v1(12.28,11.07) v1(12.28,10.61)
VDDA_ST: length 10.5
  TOP w0.254: FL3.2 12.98,9.78 13.79,10.59 v1(13.79,11.19)
  POWER w0.254: v1(13.79,11.19) 13.36,11.19 12.68,11.87 12.68,12.51 12.04,13.15 10.8,13.15 9.2,14.75 8.38,14.75 7.95,15.18 J20.1
  vias: v1(9.12,9.19) v1(11.44,8.32) v1(11.89,8.32) v1(12.36,8.32)
A0_N: length 8.7
  TOP w0.102: U1.23 v1(17.24,3.53)
  BOTTOM w0.102: v1(17.24,3.53) 16.99,3.28 16.99,3.08 15.97,2.07 15.21,2.07 15.04,1.9 14.37,1.9 14.17,1.71 13.45,1.71 13.24,1.49 11.76,1.49 11,0.73 J44.1
A1_N: length 8.1
  TOP w0.102: U1.24 v1(17.74,3.54)
  BOTTOM w0.102: v1(17.74,3.54) 16.06,1.86 15.29,1.86 15.13,1.7 14.45,1.7 14.25,1.5 13.54,1.5 13.32,1.29 12.6,1.29 12.02,0.71 J45.1
A2_N: length 7.3
  TOP w0.102: U1.25 v1(18.24,2.52)
  BOTTOM w0.102: J46.1 13.04,0.71 13.62,1.3 14.34,1.3 14.53,1.49 15.21,1.49 15.37,1.66 16.15,1.66 16.43,1.93 17.81,1.93 17.99,2.11 17.99,2.27 v1(18.24,2.52)
A3_N: length 6.7
  TOP w0.102: U1.26 v1(18.74,2.52)
  BOTTOM w0.102: v1(18.74,2.52) 17.95,1.73 16.51,1.73 16.24,1.46 15.46,1.46 15.29,1.29 14.62,1.29 14.05,0.72 J47.1
A4_N: length 6.7
  TOP w0.102: U1.28 v1(19.74,2.52)
  BOTTOM w0.102: J48.1 15.07,0.78 15.54,1.25 16.32,1.25 16.59,1.52 18.03,1.52 18.69,2.18 19.4,2.18 v1(19.74,2.52)
A5_N: length 7.1
  TOP w0.102: U1.29 v1(20.24,3.53)
  BOTTOM w0.102: v1(20.24,3.53) 20.24,2.55 19.67,1.98 18.77,1.98 18.11,1.32 16.68,1.32 16.08,0.72 J49.1
A6_N: length 7.7
  TOP w0.102: U1.30 20.74,4.1 v1(20.91,4.27)
  BOTTOM w0.102: v1(20.91,4.27) 21.09,4.45 21.9,4.45 22.77,3.58 22.77,2.5 23.71,1.56 23.71,1.23 24.21,0.72 J57.1
A7_N: length 4.3
  TOP w0.102: U1.35 v1(23.24,2.52)
  BOTTOM w0.102: v1(23.24,2.52) 24.22,1.54 24.97,1.54 25.23,1.28 J58.1
COEX0: length 10.5
  TOP w0.102: U1.93 v1(21.24,13.89)
  BOTTOM w0.102: v1(21.24,13.89) 22,13.13 28.96,13.13 J119.1
COEX1: length 9.2
  TOP w0.102: U1.92 v1(21.74,13.9)
  BOTTOM w0.102: v1(21.74,13.9) 22.3,13.34 28.8,13.34 29.29,13.83 J121.1
COEX2: length 7.1
  TOP w0.102: U1.91 v1(22.24,13.89)
  BOTTOM w0.102: J123.1 27.29,14.48 26.35,13.54 22.59,13.54 v1(22.24,13.89)
D+: length 5.3
  TOP w0.135: v1(4.61,13.15) 4.87,13.41 5.91,13.41 6.22,13.1 6.22,12.8 U4.B8
  BOTTOM w0.135: v1(4.61,13.15) 4.61,13.15 4.61,13.85 4.55,13.92 4.55,14.85 4.91,15.21 J23.1
D-: length 5.8
  TOP w0.135: v1(4.06,13.7) 4.84,13.7 6.03,13.7 6.51,13.22 6.51,12.8 U4.C8
  BOTTOM w0.135: J24.1 3.89,15.21 4.26,14.84 4.26,13.9 v1(4.06,13.7)
ENABLE: length 1.5
  TOP w0.102: U1.101 17.24,13.66 17.37,13.79 17.8,13.79 18.18,14.17 R3.2
ESIM_1V8: length 2.8
  TOP w0.188: U3.8 10.01,6.53 10.28,6.26 C25.2 C24.2 12.03,6.26 R28.2
ESIM_CLK: length 19.3
  TOP w0.102: R26.2 26.99,1.26 26.71,0.99 12.81,0.99 10.48,3.32 10.48,3.83 10.31,3.99 U3.6
ESIM_IO: length 28.6
  TOP w0.102: v1(24.99,2.54) 24.45,2.54 23.76,1.85 23.54,1.85 23.29,1.6 13.25,1.6 v1(12.44,2.4) ; U3.3 4.04,3.46 v1(3.86,3.28) ; R27.2 29.16,2.35 v1(29.16,2.42)
  BOTTOM w0.102: v1(29.16,2.42) 28.63,2.95 26.64,2.95 26.23,2.54 v1(24.99,2.54) ; v1(12.44,2.4) 9.68,2.4 9.13,1.85 5.29,1.85 v1(3.86,3.28)
ESIM_RST: length 17.6
  TOP w0.102: U3.7 9.98,5.26 10.43,4.81 10.43,4.16 10.68,3.91 10.68,3.41 12.9,1.19 23.46,1.19 23.69,1.43 R25.2
IO_SUPPLY_RSV: length 2.5
  TOP w0.188: U1.13 15.86,7.19 15.71,7.04 14.02,7.04 C9.2
MAGPIO0: length 3.6
  TOP w0.102: U1.55 v1(32.41,4.69)
  BOTTOM w0.102: J118.1 31.04,6.45 32.41,5.08 v1(32.41,4.69)
MAGPIO1: length 3.5
  TOP w0.102: U1.54 v1(32.44,4.19)
  BOTTOM w0.102: v1(32.44,4.19) 32.44,4.2 32.08,4.55 32.08,4.89 31.45,5.52 31.17,5.52 31.08,5.43 J120.1
MAGPIO2: length 3
  TOP w0.102: U1.53 v1(32.41,3.69)
  BOTTOM w0.102: J122.1 31.46,4.42 32.19,3.69 v1(32.41,3.69)
N_U545_NRST: length 1
  TOP w0.102: U1.4 15.57,11.69 R4.2
NORDICRST: length 12.2
  TOP w0.102: U1.32 C13.2 21.74,2.13 21.41,1.8 13.38,1.8 12.83,2.35 R5.1
NRF91_INT: length 17.4
  TOP w0.102: R21.1 R23.2 ; R23.2 15.53,6.1 15.62,6.19 U1.15 ; R23.2 14.88,5.76 13.83,5.76 13.37,6.22 13.37,8.25 14.94,9.82 v1(14.94,10.93)
  BOTTOM w0.102: v1(8.12,12.19) 8.54,12.62 12.17,12.62 12.95,11.84 12.95,11.21 13.56,10.6 14.61,10.6 v1(14.94,10.93)
NRF91_RSTN: length 18.3
  TOP w0.102: v1(13.33,5.47) R6.1 R5.2
  BOTTOM w0.102: J60.1 27.26,0.72 25.74,2.24 25.22,2.24 24.84,1.86 24.4,1.86 24.1,2.16 24.1,2.72 22.15,4.67 15.64,4.67 15.22,5.09 13.71,5.09 v1(13.33,5.47)
NRF91_SWDCLK: length 3.5
  TOP w0.102: U1.33 22.24,2.55 v1(22.15,2.46)
  BOTTOM w0.102: J54.1 21.16,0.72 22.15,1.71 v1(22.15,2.46)
NRF91_SWDIO: length 3.3
  TOP w0.102: v1(22.81,1.95) 22.74,2.02 U1.34
  BOTTOM w0.102: v1(22.81,1.95) 23.2,1.56 J56.1
NRF91RST: length 12.7
  TOP w0.102: R6.2 12.83,6.72 12.96,6.85 12.96,8.42 14.4,9.85 v1(14.4,10.27)
  BOTTOM w0.102: v1(8.12,11.69) 8.59,11.69 8.8,11.91 10.43,11.91 10.93,12.41 12.09,12.41 12.74,11.76 12.74,11.13 13.47,10.4 14.27,10.4 v1(14.4,10.27)
NRX: length 8.7
  TOP w0.102: R1.2 v1(14.38,12.5)
  BOTTOM w0.102: J8.1 20.15,14.51 18.01,12.37 17.54,12.37 17.16,12.74 16.42,12.74 16.17,12.5 v1(14.38,12.5)
NTX: length 9.6
  TOP w0.102: R2.2 v1(14.35,11.94)
  BOTTOM w0.102: v1(14.35,11.94) 14.71,12.3 16.26,12.3 16.5,12.54 17.08,12.54 17.45,12.17 18.11,12.17 21.15,15.21 21.15,15.99 J7.1
NTX_SRX: length 11.1
  TOP w0.102: v1(16.8,11.71) 16.32,12.19 U1.3 15.51,12.19 R2.1
  BOTTOM w0.102: v1(16.8,11.71) 16.62,11.71 14.51,9.6 9.21,9.6 v1(8.62,10.19)
OSC32_IN: length 5.1
  TOP w0.102: v1(5.38,9.02) 5.44,9.02 5.5,9.08 5.51,9.08 U4.A1
  BOTTOM w0.102: J97.1 2.37,6.96 3.18,6.96 3.33,7.1 3.33,7.49 3.74,7.9 3.92,7.9 4.47,8.45 4.81,8.45 v1(5.38,9.02)
OSC32_OUT: length 4.6
  BOTTOM w0.102: v1(6.12,9.19) 5.61,8.69 5.33,8.69 4.9,8.25 4.56,8.25 4,7.69 3.82,7.69 3.53,7.4 3.53,7.02 3.27,6.76 3.16,6.76 J99.1
P0.00: length 4.6
  TOP w0.102: J10.1 18.11,15.24 18.33,15.02 18.76,15.02 19.33,14.45 19.63,14.45 20.24,13.84 U1.95 v1(20.24,12.73)
P0.01: length 4.2
  TOP w0.102: U1.96 19.74,13.96 19.5,14.2 19.24,14.2 18.67,14.77 18.22,14.77 17.1,15.89 J11.1
P0.02: length 5
  TOP w0.102: J12.1 16.08,15.31 16.34,15.05 17.58,15.05 18.11,14.52 18.58,14.52 19.24,13.86 U1.97
P0.03: length 6.3
  TOP w0.102: U1.99 v1(18.24,13.69)
  BOTTOM w0.102: J14.1 14.05,14.76 15.12,13.69 v1(18.24,13.69)
P0.04: length 7.5
  TOP w0.102: U1.100 v1(17.74,12.73)
  BOTTOM w0.102: J15.1 13.03,14.78 14.88,12.93 16.04,12.93 16.22,13.11 17.36,13.11 v1(17.74,12.73)
P0.10: length 4.3
  TOP w0.102: U1.18 16.76,4.69 16.94,4.87 16.94,6.43 17.19,6.68 17.19,7.15 v1(17.51,7.47)
  BOTTOM w0.102: v1(17.51,7.47) J103.1
P0.11: length 3.8
  TOP w0.102: v1(17.31,6.18) 17.17,6.04 17.17,4.62 16.74,4.19 U1.19
  BOTTOM w0.102: v1(17.31,6.18) 17.58,6.45 J105.1
P0.12: length 3.6
  TOP w0.102: U1.20 16.56,3.69 17.4,4.53 17.4,5.6 v1(17.51,5.71)
  BOTTOM w0.102: J107.1 17.84,5.71 v1(17.51,5.71)
P0.21: length 1.4
  TOP w0.102: v1(24.21,3.65) 24.21,3.47 24.24,3.44 U1.37
  BOTTOM w0.102: v1(24.21,3.65) J124.1
P0.22: length 8.9
  TOP w0.102: U1.38 24.74,3.77 24.36,4.15 21.96,4.15 21.75,3.94 v1(21.75,3.62)
  BOTTOM w0.102: v1(21.75,3.62) 21.75,1.77 21.31,1.33 20.73,1.33 20.15,0.75 J53.1
P0.23: length 9.7
  TOP w0.102: v1(21.39,4.08) 21.6,4.08 21.88,4.35 24.45,4.35 25.24,3.56 U1.39
  BOTTOM w0.102: v1(21.39,4.08) 21.87,4.08 22.48,3.47 22.48,1.61 22.18,1.31 J55.1
P0.24: length 3.8
  TOP w0.102: U1.40 25.74,2.29 v1(25.36,1.91)
  BOTTOM w0.102: J59.1 26.24,1.38 25.72,1.91 v1(25.36,1.91)
P0.25: length 3.7
  TOP w0.102: U1.42 v1(26.74,2.57)
  BOTTOM w0.102: J61.1 28.27,0.72 26.74,2.26 v1(26.74,2.57)
P0.26: length 2.7
  TOP w0.102: U1.83 26.24,16 J2.1
P0.27: length 2.9
  TOP w0.102: U1.84 25.74,14.13 25.23,14.64 J3.1
P0.28: length 2.9
  TOP w0.102: J4.1 24.21,14.71 24.74,14.18 U1.86
P0.29: length 3.1
  TOP w0.102: J5.1 23.19,14.79 24.24,13.74 U1.87
P0.30: length 3.6
  TOP w0.102: J6.1 22.18,14.95 22.54,14.59 23.07,14.59 23.74,13.92 U1.88
P0.31: length 6.3
  TOP w0.102: J9.1 19.13,14.99 19.43,14.69 19.75,14.69 20.07,14.37 22.96,14.37 23.24,14.09 U1.89
PA0: length 6.7
  TOP w0.102: v1(9.45,8.34) 9.45,7.49 9.02,7.06 v1(9.02,4.78)
  BOTTOM w0.102: v1(9.45,8.34) 8.75,9.04 8.75,9.56 v1(8.61,9.69) ; J86.1 8.64,4.42 8.66,4.42 v1(9.02,4.78)
PA1: length 6.6
  TOP w0.102: U4.H2 9.45,9.36 9.45,9.06 9.25,8.86 9.14,8.86 8.91,8.62 8.91,7.52 8.55,7.16 7.63,7.16 7.4,7.39 7.2,7.39 6.8,7.39 6.47,7.06 v1(5.92,7.06)
  BOTTOM w0.102: v1(5.92,7.06) J88.1
PA4: length 6.3
  TOP w0.102: v1(6.94,7.06) 7.44,7.06 7.54,6.96 8.63,6.96 9.11,7.44 9.11,8.54 9.23,8.66 9.34,8.66 9.66,8.98 9.66,9.65 U4.H3
  BOTTOM w0.102: J90.1 v1(6.94,7.06)
PA7: length 5.9
  TOP w0.102: v1(9.45,7.01) 9.81,7.37 9.81,8.42 9.87,8.49 9.87,9.94 U4.H4
  BOTTOM w0.102: J96.1 8.89,6.45 v1(9.45,7.01)
PA8: length 1.6
  BOTTOM w0.102: v1(7.12,12.19) 6.75,12.56 6.75,12.9 6.94,13.09 J85.1
PA9: length 1.7
  BOTTOM w0.102: J87.1 6.4,13.09 6.4,12.62 6.62,12.4 v1(6.62,12.19)
PA10: length 4.7
  POWER w0.102: v1(4.03,12.52) 6.16,12.52 6.36,12.32 6.36,11.95 v1(6.62,11.69)
  BOTTOM w0.102: v1(4.03,12.52) 3.4,13.14 3.3,13.14 J89.1
PA15: length 6.7
  BOTTOM w0.102: J29.1 0.72,9.5 2.96,11.74 4.7,11.74 4.86,11.58 5.32,11.58 5.43,11.69 v1(5.62,11.69)
PB3: length 7.5
  TOP w0.102: J31.1 0.68,7.47 2.47,9.26 v1(2.47,9.52) ; U4.A5 5.62,11.17 v1(5.15,10.7)
  BOTTOM w0.102: v1(2.47,9.52) 2.69,9.52 2.77,9.6 3.25,9.6 3.65,10 3.65,10.24 3.97,10.56 5.01,10.56 v1(5.15,10.7)
PB4: length 8.1
  BOTTOM w0.102: v1(5.62,10.69) 5.28,10.36 4.06,10.36 3.86,10.16 3.86,9.92 3.33,9.39 2.86,9.39 2.6,9.14 2.4,9.14 1.96,8.7 1.96,8.41 1.33,7.78 1.33,7.06 0.72,6.45 J32.1
PB5: length 9.3
  TOP w0.102: J33.1 0.12,5.43 2.01,7.32 2.01,8.17 3.15,9.31 3.73,9.31 v1(3.94,9.52)
  POWER w0.102: v1(3.94,9.52) 4.07,9.52 4.43,9.89 5.14,9.89 5.69,10.44 6.36,10.44 v1(6.62,10.69)
PB6: length 11.3
  TOP w0.102: v1(3.43,6.05) 0.78,3.4 J35.1
  POWER w0.102: v1(5.44,8.32) 5.86,8.32 6.48,8.94 6.84,8.94 7.37,9.47 7.37,9.94 v1(7.12,10.19)
  BOTTOM w0.102: v1(3.43,6.05) 3.74,6.36 3.74,7.18 4.03,7.47 4.33,7.47 4.42,7.56 4.93,7.56 5.11,7.74 5.11,7.99 v1(5.44,8.32)
PB7: length 10
  TOP w0.102: v1(2.37,7.98) 2.37,7.12 1.19,5.94 1.19,5.48 0.12,4.42 J34.1
  POWER w0.102: v1(6.62,10.19) 6.35,9.93 5.5,9.93 5.19,9.62 4.69,9.62 4.13,9.06 3.09,9.06 2.37,8.34 v1(2.37,7.98)
PB8: length 5.9
  BOTTOM w0.102: J91.1 1.86,8.03 2.16,8.33 2.16,8.61 2.48,8.94 2.68,8.94 2.94,9.19 4.08,9.19 4.65,9.76 5.68,9.76 v1(6.12,10.19)
PB9: length 9.8
  TOP w0.102: v1(5.08,12.12) 5.08,11.14 4.79,10.85 4.79,10.57 5.17,10.19 U4.A3
  BOTTOM w0.102: v1(5.08,12.12) 5.33,12.37 5.33,13.89 5.56,14.12 6.69,14.12 6.69,14.12 8.31,14.12 8.97,14.78 J19.1
PB10: length 5.6
  TOP w0.102: v1(10.26,12.24) 10.26,12.6 10.39,12.73 10.39,14.83 9.99,15.23 J18.1
  BOTTOM w0.102: v1(10.26,12.24) 9.02,12.24 8.97,12.19 v1(8.62,12.19)
PB12: length 0.9
  TOP w0.102: v1(9.12,13.15) U4.H8
  BOTTOM w0.102: v1(9.12,13.15) 8.97,13.3 J93.1
PB13: length 10.4
  TOP w0.102: J26.1 1.45,12.55 3.72,14.81 5.71,14.81 6.27,14.25 6.57,14.25 7.56,13.26 8.05,13.26 U4.G8
PB14: length 10.2
  TOP w0.102: U4.F8 7.77,13.04 7.65,13.04 7.63,13.06 7.48,13.06 6.49,14.04 6.19,14.04 5.63,14.61 3.8,14.61 0.72,11.53 J27.1
PC0: length 7.1
  POWER w0.102: v1(7.62,10.19) 7.86,9.95 7.86,8.41 v1(7.93,8.34)
  BOTTOM w0.102: v1(7.93,8.34) 7.93,8.18 7.45,7.7 7.45,6.11 7.29,5.95 6.61,5.95 6.41,5.75 6.41,4.91 J75.1
PC1: length 5.1
  BOTTOM w0.102: v1(7.62,9.69) 7.62,8.5 7.59,8.47 7.59,8.18 6.43,7.02 6.43,6.1 6.3,5.97 6.02,5.97 5.92,5.87 J76.1
PC2: length 11.9
  TOP w0.102: v1(10.78,8.06) 10.78,8.25 10.69,8.34 10.69,10.93 10.6,11.02 10.6,14.2 11,14.6 J17.1
  BOTTOM w0.102: v1(10.78,8.06) 10.5,8.06 10.45,8.01 9.31,8.01 9.11,8.21 9.11,8.39 8.54,8.96 8.54,9.27 v1(8.12,9.69)
PC3: length 13
  TOP w0.102: U4.G1 8.62,9.18 v1(8.17,8.74) ; v1(10.97,7.64) 11.12,7.79 11.12,8.2 10.89,8.43 10.89,11.01 10.8,11.1 10.8,14.11 12.02,15.33 J16.1
  BOTTOM w0.102: v1(8.17,8.74) 8.48,8.74 8.91,8.3 8.91,8.12 9.22,7.81 10.54,7.81 10.71,7.64 v1(10.97,7.64)
PC4: length 7.3
  TOP w0.102: U4.H5 10.08,10.23 10.08,8.4 10.01,8.33 10.01,7.29 9.94,7.21 v1(9.94,7.02)
  BOTTOM w0.102: J77.1 8.57,6.05 8.97,6.05 v1(9.94,7.02)
PC5: length 10
  TOP w0.102: v1(10.46,6.78) 10.46,6.78 10.46,6.96 10.21,7.21 10.21,8.25 10.28,8.32 10.28,10.53 U4.H6
  BOTTOM w0.102: J78.1 7.43,4.94 8.36,4.94 9.95,6.53 10.21,6.53 v1(10.46,6.78)
PC8: length 1
  BOTTOM w0.102: v1(7.62,12.69) 7.62,13.23 J72.1
PC10: length 6.9
  BOTTOM w0.102: v1(6.12,12.19) 5.64,12.19 5.24,11.78 4.94,11.78 4.78,11.94 2.88,11.94 1.45,10.52 J28.1
PC11: length 8
  BOTTOM w0.102: v1(6.12,11.69) 5.78,11.36 4.79,11.36 4.62,11.53 3.04,11.53 1.33,9.82 1.33,9.09 0.72,8.48 J30.1
PC12: length 5.4
  TOP w0.102: v1(3.48,12.55) v1(3.48,11)
  POWER w0.102: v1(6.62,11.19) 6.36,10.94 3.54,10.94 3.48,11 v1(3.48,11)
  BOTTOM w0.102: v1(3.48,12.55) J73.1
PC13: length 3.7
  TOP w0.102: v1(4.92,9.06) 5.17,9.31 5.18,9.31 5.2,9.34 5.26,9.34 U4.A2
  BOTTOM w0.102: J74.1 3.51,8.1 3.83,8.1 4.39,8.66 4.52,8.66 v1(4.92,9.06)
PD2: length 4
  BOTTOM w0.102: v1(6.12,11.19) 5.9,11.19 5.87,11.16 4.7,11.16 4.53,11.33 3.13,11.33 2.87,11.07 J83.1
PH3: length 6.5
  TOP w0.102: v1(1.86,11.68) 2.26,11.68 2.69,11.25 2.69,10.61 R7.2 3.69,9.94 3.78,10.02 v1(4.19,10.02)
  BOTTOM w0.102: v1(6.12,10.69) 5.44,10.02 v1(4.19,10.02) ; v1(1.86,11.68) J95.1
SCLK: length 6
  TOP w0.102: v1(31.31,4.08) 30.98,4.41 30.98,5.87 31.3,6.19 U1.58
  BOTTOM w0.102: v1(31.31,4.08) 31.31,2.45 31.82,1.94 31.96,1.94 J112.1
SDATA: length 7.5
  TOP w0.102: v1(30.96,3.77) 30.77,3.96 30.77,5.95 31.51,6.69 U1.59
  BOTTOM w0.102: v1(30.96,3.77) 31.11,3.63 31.11,2.37 31.88,1.59 31.88,1.01 J114.1
SIM_1V8: length 26.7
  TOP w0.102: R28.1 12.27,4.93 12.11,4.77 12.11,2.27 12.98,1.39 23.37,1.39 23.63,1.65 24.03,1.65 v1(24.59,2.21) ; v1(29.98,3.71) 30.24,3.45 U1.49 30.24,2.75 30.5,2.49 v1(31.74,2.49) 31.74,2.36 32.01,2.09 D4.1
  BOTTOM w0.102: v1(31.74,2.49) 31.78,2.53 J131.1 ; v1(24.59,2.21) 24.59,2.66 24.8,2.87 26.12,2.87 26.52,3.27 29.54,3.27 v1(29.98,3.71)
SIM_CLK: length 4.7
  TOP w0.102: v1(28.83,2.08) 28.32,2.08 D2.1 ; R26.1 27.75,1.81 28.02,2.08 D2.1 ; D2.1 28.17,2.46 28.32,2.61 28.53,2.61 28.74,2.82 U1.46
  BOTTOM w0.102: J128.1 29.74,2.08 v1(28.83,2.08)
SIM_IO: length 3.8
  TOP w0.102: v1(30.85,2.09) 30.83,2.09 D3.1 30.35,2.09 ; 30.35,2.09 30.21,2.09 29.55,1.43 R27.1 ; 30.35,2.09 30.35,2.35 30.21,2.49 29.87,2.49 29.74,2.62 U1.48
  BOTTOM w0.102: J130.1 30.41,2.53 v1(30.85,2.09)
SIM_RST: length 6.9
  TOP w0.102: U1.43 v1(27.24,2.43) 26.89,2.08 D1.2 26.16,2.08 25.84,1.75 25.74,1.75 R25.1
  BOTTOM w0.102: v1(27.24,2.43) 27.94,1.73 29.36,1.73 29.85,1.24 29.85,0.96 J126.1
STX_NRX: length 12
  TOP w0.102: v1(16.81,12.19) 16.31,12.69 U1.2 15.46,12.69 R1.1
  BOTTOM w0.102: v1(16.81,12.19) 14.42,9.8 9.48,9.8 8.75,10.53 8.45,10.53 v1(8.12,10.19)
U545_INT: length 18.8
  TOP w0.102: v1(14.45,10.93) 14.74,10.65 14.74,9.9 13.17,8.33 13.17,6.11 14.18,5.09 14.89,5.09 15.22,4.76 ; 15.22,4.76 R24.2 ; 15.22,4.76 R22.1 15.49,5.69 U1.16
  BOTTOM w0.102: v1(14.45,10.93) 14.45,10.93 14.15,10.93 14.02,10.8 13.64,10.8 13.15,11.29 13.15,11.92 12.26,12.82 8.45,12.82 8.16,12.53 7.98,12.53 7.8,12.35 7.44,12.35 v1(7.11,12.68)
U545_NRST: length 24.9
  TOP w0.102: R4.1 14.37,11.38 14.12,11.13 14.12,10.46 14.07,10.41 14.07,9.81 12.76,8.5 12.76,6.99 12.52,6.75 11.14,6.75 v1(10.54,7.35) 10.54,7.7 10.42,7.83 10.42,8.17 10.48,8.23 10.48,10.85 9.88,11.45 9.88,12.66 10.09,12.87 10.09,14.49 9.86,14.72 8.25,14.72 7.98,14.45 D5.1 7.59,14.78 6.94,15.43 J21.1 ; U4.E1 7.62,8.54 7.49,8.41 R8.1 8.05,7.83 8.05,7.5 v1(8.05,7.5)
  BOTTOM w0.102: v1(10.54,7.35) 10.19,7.35 10.03,7.5 v1(8.05,7.5)
U545_SWDCLK: length 32.8
  TOP w0.102: v1(4.98,7.18) 4.84,7.32 4.84,7.32 4.41,7.75 4.41,9.02 4.72,9.33 4.72,10.35 4.59,10.49 4.59,12.12 4.96,12.49 5.32,12.49 U4.A7
  BOTTOM w0.102: v1(4.98,7.18) 4.66,6.85 4.66,3.5 5.5,2.65 8.74,2.65 9.72,3.64 16.3,3.64 17.13,4.47 20.14,4.47 20.84,3.77 20.84,2.38 19.86,1.4 19.32,1.4 19.13,1.21 J52.1
U545_SWDIO: length 33.3
  TOP w0.102: v1(4.51,7.18) 4.21,7.48 4.21,9.11 4.52,9.42 4.52,10.27 4.38,10.41 4.38,12.2 4.87,12.69 U4.A8
  BOTTOM w0.102: v1(4.51,7.18) 4.45,7.12 4.45,3.42 5.42,2.45 8.82,2.45 9.8,3.43 16.38,3.43 17.21,4.26 20.06,4.26 20.64,3.69 20.64,2.46 19.77,1.6 18.99,1.6 18.11,0.72 J51.1
VCAP: length 2.2
  TOP w0.254: U4.H7 9.31,12.19 9.57,12.45 C23.2
VIO: length 3.6
  TOP w0.102: U1.57 v1(32.41,5.69)
  BOTTOM w0.102: v1(32.41,5.69) 32.41,6.03 30.97,7.47 J116.1
N13496579: length 3.4
  TOP w0.188: C2.2 33.51,11.34 arc(33.34,10.9) 32.91,10.69 U1.67
N13625908: length 2.9
  TOP w0.188: J65.2 34.7,3.9 arc(34.48,3.87) 34.29,3.77 arc(34.09,3.68) 33.87,3.65 L5.1 C66.2
N13629219: length 2.1
  TOP w0.188: J63.1 36.37,6.44 L3.1 C65.2
N13629615: length 3
  TOP w0.188: J66.2 C6.2 34.07,12.71 C2.1 34.07,12.73 L1.1
N13629622: length 5.4
  TOP w0.188: C6.1 34.07,10.56 arc(34.35,9.89) 35.02,9.61 J64.1
N13657158: length 3.3
  TOP w0.188: R9.2 R10.1 33.58,6.43 33.58,7.17 arc(33.43,7.54) 33.06,7.69 32.35,7.69 32.35,7.69 U1.61
N13657162: length 1.1
  TOP w0.188: R9.1 C65.1 L2.1
N13659178: length 1.1
  TOP w0.188: C66.1 L4.1 R10.2

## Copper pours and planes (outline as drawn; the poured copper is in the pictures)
GND on TOP: 37.72,15.8 37.72,0.2 0.2,0.2 0.2,15.8 ; 8 cut-outs
GND on BOTTOM: 37.72,15.8 37.72,0.2 0.2,0.2 0.2,15.8 ; 7 cut-outs
GND on GND, POWER: 0.2,15.8 37.72,15.8 37.72,10.13 37.36,9.61 37.72,9.09 37.72,6.95 37.46,6.75 37.37,6.44 37.46,6.13 37.72,5.93 37.72,0.2 0.2,0.2
VDD on TOP: 17.11,14.93 16.51,14.93 16.48,14.9 16.48,13.07 16.59,12.96 16.97,12.96 17.02,13.01 17.02,13.66 17.18,13.82 17.18,14.86
VDD NRF91 on TOP: 31.06,14.69 32.59,14.69 32.59,14.2 32.29,13.9 31.09,13.9 30.95,14.04 30.95,14.58
VDD NRF91 on TOP: 14.34,3.34 13.25,3.34 13.13,3.22 13.13,2.15 13.31,1.97 16.8,1.97 17.01,2.18 17.01,3.32 16.92,3.41 16.59,3.41 16.49,3.31 16.49,2.85 16.34,2.7 15.51,2.7 15.17,3.04 14.64,3.04
VDD NRF91 on TOP: 14.16,7.27 14.24,7.19 15.53,7.19 15.83,7.49 16.82,7.49 16.91,7.58 16.91,7.82 16.8,7.93 15.78,7.93 15.47,8.24 14.35,8.24 14.17,8.06 14.17,7.28
VDD NRF91 on TOP: 13.18,14.93 16.24,14.93 16.36,14.81 16.36,13.91 16.27,13.82 14.91,13.82 14.73,13.64 14.21,13.64 14.11,13.54 14.11,13.27 14.04,13.2 12.96,13.2 12.78,13.38 12.78,14.53
VDD NRF91 on POWER: 13.9,15.04 32.3,15.04 32.62,14.72 32.62,13.45 30.52,11.35 21.82,11.35 16.79,6.32 16.79,3.19 15.84,2.24 11.66,2.24 9.34,-0.08 6.49,-0.08 6.42,-0.01 6.42,1.95 12.8,8.33 12.8,12.74 12.57,12.97 12.57,13.71
VDD_ST on TOP: 11.93,13.94 11.01,13.94 10.96,13.89 10.96,9.44 11.18,9.22 12.03,9.22 12.54,9.73 12.54,11.71 12,12.25 12,13.87
VDD_ST on TOP: 5.61,8.16 5.61,7.62 5.76,7.47 6.69,7.47 7.38,8.16 7.38,8.7 7.29,8.79 6.24,8.79
VDD_ST on BOTTOM: 12.62,11.68 12.62,10.13 12.44,9.95 9.55,9.95 9.05,10.45 7.54,10.45 7.38,10.61 7.38,11.78 7.51,11.91 7.71,11.91 7.88,11.74 7.88,11.63 8,11.51 8.69,11.51 9.07,11.89 10.33,11.89 10.77,12.33 11.97,12.33
VDD_ST on BOTTOM: 7.34,9.89 6.96,9.89 6.85,9.78 6.85,9.4 5.61,8.16 5.61,7.7 5.73,7.58 6,7.58 6.45,8.03 7.25,8.03 7.38,8.16 7.38,9.85
VDD_ST on POWER: 4.28,-0.04 2.49,-0.04 2.39,0.06 2.39,4.61 10.99,13.21 12.13,13.21 12.56,12.78 12.56,8.24
VDDA_ST on TOP: 12.03,9.16 11.27,9.16 11.19,9.08 11.19,8.2 11.34,8.05 12.54,8.05 12.64,8.15 12.64,8.58 13.23,9.17 13.35,9.17 13.52,9.34 13.52,10.22 13.38,10.36 12.49,10.36 12.39,10.26 12.39,9.52
VDDA_ST on BOTTOM: 12.64,9.05 12.64,8.17 12.52,8.05 11.19,8.05 10.89,8.35 9.61,8.35 8.9,9.06 8.9,9.28 9.02,9.4 12.29,9.4
